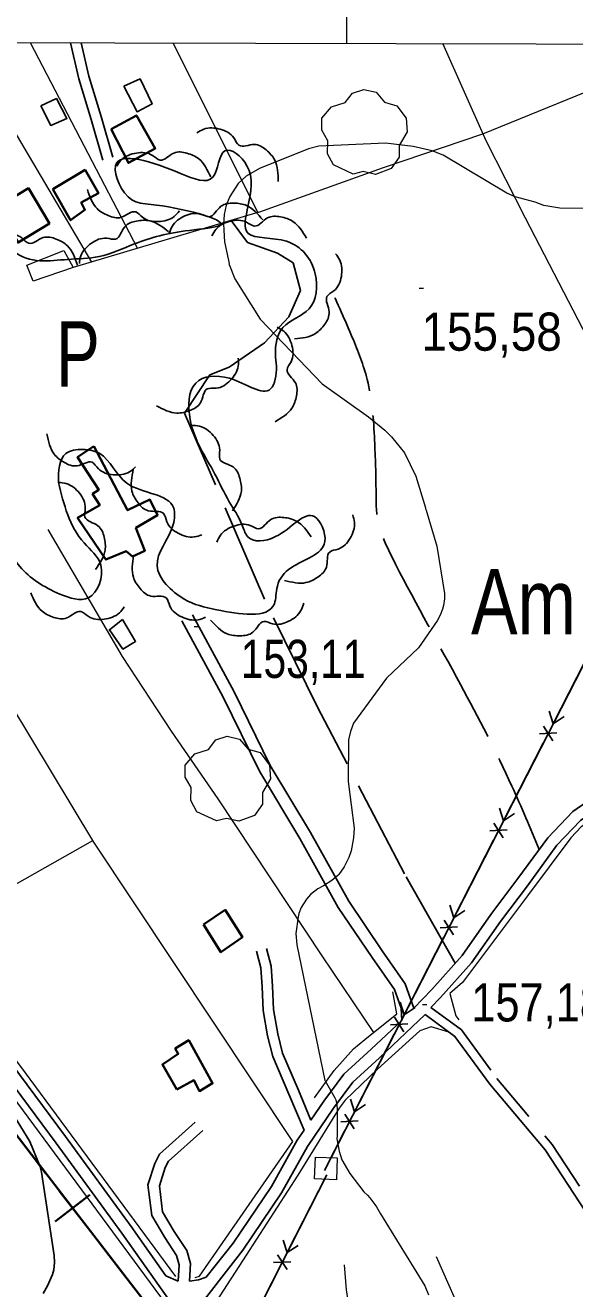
# Model space of a CAD drawing. Extents: x 480269 to 484877, y 4383588 to 4386804.
# Drawn here: x 481926.2 to 482052.3, y 4386167.5 to 4386457.3 of the extents above; entities that cross this region are included whole.
import ezdxf
from ezdxf.enums import TextEntityAlignment as Align

# ---------------------------------------------------------------- set-up
doc = ezdxf.new("R2010")
doc.units = 0
doc.header["$LTSCALE"] = 3.8
doc.linetypes.add('LONG_DASHED', pattern=[7.5, 6, -1.5])
doc.linetypes.add('MEDIUM_DASHED', pattern=[4.5, 3, -1.5])
for name, color, linetype, lineweight in [('1', 7, 'Continuous', 13), ('21', 7, 'Continuous', 25), ('25', 7, 'LONG_DASHED', 25), ('27', 7, 'Continuous', 25), ('29', 7, 'Continuous', 13), ('34', 7, 'Continuous', 35), ('38', 7, 'Continuous', 25), ('43', 7, 'Continuous', 25), ('47', 7, 'Continuous', 35), ('51', 7, 'Continuous', 13), ('7', 7, 'Continuous', 13), ('8', 7, 'Continuous', 25), ('9', 7, 'Continuous', 13)]:
    doc.layers.add(name, color=color, linetype=linetype, lineweight=lineweight)
doc.layers.add('31', color=7, linetype='Continuous')

msp = doc.modelspace()

# ---------------------------------------------------------------- linework, layer by layer
at = {"layer": '1'}
msp.add_line((482000, 4386453.1), (482000, 4386524.51), dxfattribs=at)
msp.add_lwpolyline([(480529.1, 4386456.6), (484105.5, 4386448.1), (484100.5, 4384135.8), (480523.1, 4384144.4)], close=True, dxfattribs=at)
at = {"layer": '21'}
for points in [[(481948.88, 4386443.31), (481951.89, 4386437.43), (481955.32, 4386439.2), (481952.57, 4386444.96)], [(481929.84, 4386438.77), (481932.1, 4386434.27), (481935.79, 4386435.9), (481933.4, 4386440.43)], [(481948.58, 4386320.95), (481951.55, 4386315.92), (481948.65, 4386314.18), (481945.56, 4386318.6)]]:
    msp.add_lwpolyline(points, close=True, dxfattribs=at)
at = {"layer": '25'}
msp.add_lwpolyline([(482024.84, 4386242.11), (482013.25, 4386262.59), (481993.26, 4386300.87), (481981.09, 4386325.62), (481962.8, 4386368.28), (481968.62, 4386377.07), (481973.05, 4386378.81), (481981.14, 4386384.42), (481986.72, 4386390.39), (481989.37, 4386396.4), (481987.72, 4386402.73), (481984.11, 4386405), (481977.23, 4386407.44), (481973.49, 4386412.5)], dxfattribs=at)
at = {"layer": '27'}
for points in [[(481965.63, 4386432.55), (481967.18, 4386433.41), (481970.98, 4386433.41), (481974.09, 4386431.43), (481975.25, 4386429.73), (481978.8, 4386429.91), (481981.5, 4386428.65), (481983.46, 4386426.35), (481984.27, 4386421.45)], [(481933.85, 4386352.38), (481939.74, 4386338.52), (481943.59, 4386333.4), (481940.75, 4386325.96), (481934.19, 4386326.79), (481925, 4386333.08), (481919.03, 4386350.08), (481914, 4386376.47), (481905.71, 4386382.56), (481891.92, 4386382.18), (481883.24, 4386378.3), (481881.08, 4386376.53), (481888.89, 4386360.03), (481903.22, 4386338.79), (481908.12, 4386325.76), (481906.15, 4386325), (481891.16, 4386335.05), (481883.69, 4386346.3), (481878.85, 4386354.87), (481871.54, 4386366.67), (481859.63, 4386367.99), (481852.4, 4386359.85), (481849.08, 4386354.52), (481843.2, 4386359.68), (481828.08, 4386359.42), (481826.24, 4386360.95), (481832.78, 4386366.42), (481846.83, 4386373.67), (481847.08, 4386376.88), (481846.69, 4386386.62), (481854.97, 4386387.4), (481860.65, 4386383.43), (481884.1, 4386388.3), (481894.03, 4386391.89), (481908.9, 4386395.37), (481914.31, 4386405.74), (481914.73, 4386414.05), (481923.39, 4386405.51), (481935.94, 4386403.55), (481943.21, 4386404.22), (481951.28, 4386407.11), (481963.89, 4386410.21), (481970.84, 4386411.41), (481955.1, 4386416.18), (481950.67, 4386417.23), (481946.94, 4386424.99), (481961.83, 4386423.29), (481969.28, 4386422.43), (481972.04, 4386428.47), (481977.09, 4386425.03), (481977.38, 4386409.52), (481986.17, 4386407.71), (481992.75, 4386400.23), (481991.34, 4386392.2), (481985.35, 4386387.92), (481983.62, 4386381.84), (481983.84, 4386379.05), (481982.52, 4386373.84), (481973.09, 4386376.28), (481965.35, 4386375.19), (481964.06, 4386366.87), (481969.75, 4386354.31), (481973.04, 4386347.96), (481975.95, 4386342.73), (481977.21, 4386340.01), (481983.66, 4386339.96), (481992.58, 4386344.55), (481994.96, 4386338.82), (481987.21, 4386332.83), (481984.07, 4386328.63), (481983.38, 4386324.54), (481970.2, 4386323.19), (481962.67, 4386325.66), (481956.48, 4386333.28), (481960.18, 4386342.74), (481960.29, 4386346.51), (481949.55, 4386352.22), (481943.31, 4386359.03), (481939.45, 4386359.96), (481935.55, 4386359), (481933.85, 4386352.38)], [(481947.24, 4386424.97), (481948.3, 4386426.38), (481951.76, 4386427.94), (481955.42, 4386427.41), (481957.17, 4386426.33), (481960.33, 4386427.95), (481963.32, 4386427.91), (481966.05, 4386426.61), (481968.79, 4386422.48)], [(481961.61, 4386414.67), (481960.38, 4386413.39), (481956.77, 4386412.24), (481953.2, 4386413.19), (481951.58, 4386414.46), (481948.25, 4386413.21), (481945.29, 4386413.6), (481942.73, 4386415.2), (481940.48, 4386419.62)], [(481959.26, 4386409.47), (481959.93, 4386411.12), (481962.87, 4386413.51), (481966.54, 4386413.94), (481968.5, 4386413.35), (481971.14, 4386415.73), (481974.04, 4386416.46), (481977.01, 4386415.91), (481980.73, 4386412.63)], [(481938.66, 4386402.59), (481938.99, 4386404.34), (481941.41, 4386407.26), (481944.92, 4386408.4), (481946.97, 4386408.21), (481949.09, 4386411.06), (481951.78, 4386412.35), (481954.81, 4386412.39), (481959.1, 4386409.9)], [(481969.05, 4386408.94), (481969.99, 4386410.45), (481973.3, 4386412.31), (481976.99, 4386412.1), (481978.82, 4386411.19), (481981.83, 4386413.08), (481984.81, 4386413.31), (481987.64, 4386412.26), (481990.75, 4386408.39)], [(481917.05, 4386406.89), (481918.25, 4386408.19), (481921.85, 4386409.4), (481925.43, 4386408.5), (481927.07, 4386407.26), (481930.38, 4386408.56), (481933.34, 4386408.22), (481935.93, 4386406.65), (481938.25, 4386402.27)], [(481997.42, 4386404.86), (481998.41, 4386403.39), (481998.75, 4386399.61), (481997.05, 4386396.33), (481995.46, 4386395.03), (481995.96, 4386391.51), (481994.94, 4386388.7), (481992.82, 4386386.55), (481988.02, 4386385.3)], [(481984.04, 4386388.01), (481985.55, 4386387.08), (481987.42, 4386383.78), (481987.22, 4386380.09), (481986.31, 4386378.25), (481988.22, 4386375.25), (481988.45, 4386372.27), (481987.41, 4386369.44), (481983.55, 4386366.32)], [(481975.11, 4386380.88), (481975.1, 4386379.1), (481973.26, 4386375.78), (481970.02, 4386374.02), (481967.97, 4386373.84), (481966.41, 4386370.64), (481963.99, 4386368.89), (481961.03, 4386368.3), (481956.35, 4386369.96)], [(481964.44, 4386365.46), (481966.2, 4386365.31), (481969.36, 4386363.2), (481970.85, 4386359.82), (481970.86, 4386357.77), (481973.91, 4386355.94), (481975.46, 4386353.39), (481975.81, 4386350.39), (481973.76, 4386345.87)], [(481951.55, 4386355.96), (481950.17, 4386354.84), (481946.44, 4386354.16), (481943.02, 4386355.55), (481941.58, 4386357.02), (481938.12, 4386356.21), (481935.23, 4386356.97), (481932.89, 4386358.88), (481931.22, 4386363.55)], [(481966.72, 4386340.39), (481965.02, 4386339.9), (481961.32, 4386340.74), (481958.72, 4386343.37), (481957.97, 4386345.28), (481954.47, 4386345.89), (481952.11, 4386347.72), (481950.71, 4386350.4), (481951.01, 4386355.36)], [(481933.85, 4386352.38), (481935.61, 4386352.15), (481938.67, 4386349.91), (481940.01, 4386346.47), (481939.94, 4386344.42), (481942.91, 4386342.46), (481944.35, 4386339.85), (481944.56, 4386336.83), (481942.33, 4386332.4)], [(481970.19, 4386338.7), (481971, 4386340.28), (481974.14, 4386342.4), (481977.84, 4386342.51), (481979.74, 4386341.75), (481982.58, 4386343.88), (481985.53, 4386344.35), (481988.44, 4386343.54), (481991.86, 4386339.94)], [(482001.36, 4386344.97), (482001.77, 4386343.24), (482000.76, 4386339.58), (481998.03, 4386337.11), (481996.08, 4386336.44), (481995.31, 4386332.97), (481993.38, 4386330.7), (481990.64, 4386329.42), (481985.7, 4386329.94)], [(481967.56, 4386321.47), (481965.88, 4386320.89), (481962.14, 4386321.54), (481959.41, 4386324.03), (481958.57, 4386325.9), (481955.04, 4386326.33), (481952.59, 4386328.04), (481951.05, 4386330.64), (481951.09, 4386335.61)], [(481948.95, 4386323.86), (481947.83, 4386322.47), (481944.32, 4386321.04), (481940.69, 4386321.69), (481938.98, 4386322.82), (481935.76, 4386321.31), (481932.78, 4386321.45), (481930.1, 4386322.84), (481927.49, 4386327.06)], [(481990.11, 4386324.69), (481989.49, 4386323.03), (481986.63, 4386320.54), (481982.98, 4386319.98), (481981, 4386320.51), (481978.44, 4386318.04), (481975.57, 4386317.22), (481972.58, 4386317.67), (481968.75, 4386320.83)]]:
    msp.add_spline(points, degree=3, dxfattribs=at)
at = {"layer": '29'}
for points in [[(482001.49, 4386423.13), (481996.95, 4386425.25), (481995.54, 4386427.79), (481995.64, 4386430.77), (481994.27, 4386433.18), (481994.31, 4386435.93), (481996.47, 4386438.53), (481999.66, 4386439.53), (482001.31, 4386441.72), (482003.88, 4386442.55), (482006.74, 4386441.9), (482008.69, 4386439.63), (482011.5, 4386438.81), (482013.63, 4386435.96), (482013.87, 4386432.83), (482011.99, 4386429.68), (482011.99, 4386427), (482010.17, 4386424.39), (482006.55, 4386423.05), (482003.78, 4386423.68)], [(481970.14, 4386274.75), (481965.6, 4386276.87), (481964.19, 4386279.41), (481964.29, 4386282.39), (481962.92, 4386284.8), (481962.96, 4386287.55), (481965.12, 4386290.15), (481968.31, 4386291.15), (481969.96, 4386293.34), (481972.53, 4386294.17), (481975.39, 4386293.52), (481977.34, 4386291.25), (481980.15, 4386290.43), (481982.28, 4386287.58), (481982.52, 4386284.45), (481980.64, 4386281.3), (481980.64, 4386278.62), (481978.82, 4386276.01), (481975.2, 4386274.67), (481972.43, 4386275.3)]]:
    msp.add_lwpolyline(points, close=True, dxfattribs=at)
at = {"layer": '34'}
for p, q in [((481924.89, 4386201.82), (481930.99, 4386193.9)), ((481933.13, 4386182.92), (481941.06, 4386189.02)), ((481934.04, 4386189.94), (481940.15, 4386182.01)), ((481943.2, 4386178.05), (481949.3, 4386170.13))]:
    msp.add_line(p, q, dxfattribs=at)
msp.add_lwpolyline([(481732.67, 4386453.74), (481770, 4386403), (482108, 4385964), (482722, 4385145)], dxfattribs=at)
at = {"layer": '38'}
msp.add_line((481958.52, 4386170.44), (481961.32, 4386169.19), dxfattribs=at)
for points in [[(481739.02, 4386453.72), (481746.6, 4386443.81), (481763.9, 4386421.1), (481780.66, 4386400.62), (481800.54, 4386375.74), (481816.44, 4386355.57), (481830.64, 4386336.1), (481844.6, 4386317.88), (481859.91, 4386297.65), (481877.97, 4386274.55), (481894.23, 4386252.79), (481912.43, 4386228.94), (481933.35, 4386200.86), (481948.43, 4386180.22), (481961.29, 4386161.94)], [(481939.06, 4386453.25), (481940.8, 4386445.59), (481943.63, 4386436.32), (481946.35, 4386426.97)], [(481782.92, 4386401.98), (481802.59, 4386377.37), (481818.53, 4386357.15), (481832.74, 4386337.67), (481846.68, 4386319.47), (481861.98, 4386299.25), (481880.05, 4386276.14), (481896.32, 4386254.37), (481914.52, 4386230.51), (481935.46, 4386202.41), (481950.56, 4386181.75), (481958.52, 4386170.44)], [(482198.57, 4386347.37), (482144.8, 4386321.02), (482124.83, 4386311.36), (482105.3, 4386301.8), (482096.79, 4386298.1), (482086.59, 4386294.29), (482075.34, 4386290.26), (482066.02, 4386286.27), (482058.26, 4386281.34), (482051.85, 4386276.96), (482046.13, 4386270.92), (482039.27, 4386261.52), (482033.05, 4386253.31), (482026.46, 4386243.91), (482019.48, 4386236.12), (482015.41, 4386231.85)], [(481964.6, 4386322.02), (481974.14, 4386304.4), (481982.43, 4386287.49), (481991.67, 4386272.12), (482000.44, 4386256.38), (482008.14, 4386245), (482013.41, 4386237.38), (482015.41, 4386231.85)], [(481962.15, 4386320.69), (481971.66, 4386303.13), (481979.98, 4386286.15), (481989.26, 4386270.73), (481998.06, 4386254.92), (482005.84, 4386243.43), (482010.91, 4386236.1), (482012.45, 4386231.85), (482012.6, 4386229.01)], [(482019.28, 4386231.97), (482021.47, 4386234.28), (482028.6, 4386242.22), (482035.25, 4386251.71), (482041.45, 4386259.9), (482048.22, 4386269.18), (482053.62, 4386274.89), (482059.75, 4386279.07), (482067.29, 4386283.86), (482076.34, 4386287.73), (482078.56, 4386288.52)], [(481981.6, 4386245.51), (481982.63, 4386241.45), (481982.96, 4386236.83), (481983.21, 4386231.5), (481984.16, 4386225.92), (481985.27, 4386221.47), (481988.9, 4386213.01), (481991.79, 4386206.15)], [(481964.71, 4386161.53), (481976.12, 4386176.27), (481985.04, 4386189.49), (481990.95, 4386200.09), (481996.94, 4386208.9), (482001.36, 4386214.86), (482007.47, 4386220.39), (482017.96, 4386230.35)], [(482012.6, 4386229.01), (482005.62, 4386222.38), (481999.34, 4386216.69), (481994.72, 4386210.48), (481991.79, 4386206.15)], [(482017.96, 4386230.35), (482024.8, 4386225.32), (482032.82, 4386214.38), (482045.48, 4386199.29), (482056.03, 4386183.18), (482065.57, 4386170.43), (482076.34, 4386154.94), (482088.98, 4386138), (482103.7, 4386117.74), (482125.67, 4386086.96), (482159.57, 4386041.91), (482175.62, 4386019.95), (482188.51, 4386002.59), (482205.17, 4385980.34)], [(481963.91, 4386169.23), (481964.15, 4386173.24), (481963.32, 4386176.2), (481960.43, 4386180.59), (481957.76, 4386185.08), (481957.01, 4386191.08), (481958.33, 4386195.23), (481959.1, 4386196.75), (481966.94, 4386203.76)], [(481990.19, 4386203.83), (481988.63, 4386201.51), (481982.72, 4386190.91), (481973.95, 4386177.92), (481967.74, 4386170.08)], [(481963.91, 4386169.23), (481965.98, 4386169.51), (481967.74, 4386170.08)]]:
    msp.add_lwpolyline(points, dxfattribs=at)
at = {"layer": '38', "linetype": 'MEDIUM_DASHED'}
for points in [[(481936.63, 4386453.25), (481938.5, 4386444.98), (481941.35, 4386435.64), (481944.07, 4386426.31)], [(481979.31, 4386244.92), (481980.28, 4386241.07), (481980.6, 4386236.69), (481980.85, 4386231.25), (481981.84, 4386225.43), (481983.02, 4386220.71), (481986.72, 4386212.08), (481990.19, 4386203.83)], [(482019.28, 4386231.97), (482026.29, 4386226.81), (482034.45, 4386215.66), (482047.15, 4386200.54), (482057.73, 4386184.38), (482067.26, 4386171.65), (482078.03, 4386156.16), (482090.65, 4386139.24), (482105.39, 4386118.96), (482127.35, 4386088.19), (482161.24, 4386043.15), (482177.29, 4386021.19), (482190.18, 4386003.84), (482206.83, 4385981.59)], [(481961.32, 4386169.19), (481961.55, 4386172.96), (481960.94, 4386175.12), (481958.24, 4386179.22), (481955.26, 4386184.22), (481954.38, 4386191.32), (481955.93, 4386196.21), (481957.02, 4386198.35), (481965.22, 4386205.68)]]:
    msp.add_lwpolyline(points, dxfattribs=at)
at = {"layer": '38', "linetype": 'LONG_DASHED'}
msp.add_spline([(482044.17, 4386268.23), (482037.88, 4386282.73), (482026.1, 4386306.05), (482011.21, 4386333.62), (482006.91, 4386345.18), (482006.71, 4386350.1), (482006.37, 4386362.09), (482004.68, 4386376.04), (482001.26, 4386385.67), (481996.06, 4386397.41)], degree=3, dxfattribs=at)
at = {"layer": '43'}
for p, q in [((482090.68, 4386381.61), (481994.87, 4386194.6)), ((482056.48, 4386314.86), (482047.36, 4386297.06)), ((482047.36, 4386297.06), (482046.44, 4386299.91)), ((482047.36, 4386297.06), (482049.88, 4386298.69)), ((482045.13, 4386296.52), (482047.3, 4386293.16)), ((482045.08, 4386292.61), (482035.96, 4386274.81)), ((482044.22, 4386294.74), (482048.21, 4386294.94)), ((482035.96, 4386274.81), (482035.04, 4386277.66)), ((482035.96, 4386274.81), (482038.48, 4386276.44)), ((482032.82, 4386272.49), (482036.81, 4386272.69)), ((482033.73, 4386274.27), (482035.9, 4386270.91)), ((482033.68, 4386270.36), (482024.56, 4386252.56)), ((482024.56, 4386252.56), (482023.64, 4386255.41)), ((482022.33, 4386252.02), (482024.5, 4386248.66)), ((482024.56, 4386252.56), (482027.09, 4386254.19)), ((482021.42, 4386250.24), (482025.41, 4386250.44)), ((482022.28, 4386248.11), (482013.17, 4386230.31)), ((482013.17, 4386230.31), (482012.25, 4386233.16)), ((482013.17, 4386230.31), (482015.69, 4386231.94)), ((482010.93, 4386229.77), (482013.1, 4386226.41)), ((482010.89, 4386225.86), (482001.77, 4386208.06)), ((482010.02, 4386227.99), (482014.01, 4386228.19)), ((482001.77, 4386208.06), (482000.85, 4386210.91)), ((482001.77, 4386208.06), (482004.29, 4386209.69)), ((481998.62, 4386205.74), (482002.61, 4386205.94)), ((481999.53, 4386207.52), (482001.7, 4386204.16)), ((481999.49, 4386203.61), (481994.87, 4386194.6)), ((481995.46, 4386193.59), (481699.21, 4385614.13)), ((481995.46, 4386193.59), (481986.36, 4386175.78)), ((481986.36, 4386175.78), (481985.43, 4386178.63)), ((481986.36, 4386175.78), (481988.87, 4386177.41)), ((481983.21, 4386173.46), (481987.2, 4386173.66)), ((481984.12, 4386175.24), (481986.29, 4386171.88)), ((481984.08, 4386171.33), (481974.98, 4386153.52))]:
    msp.add_line(p, q, dxfattribs=at)
at = {"layer": '43', "lineweight": 13}
msp.add_lwpolyline([(481992.61, 4386192.64), (481992.79, 4386197.64), (481997.79, 4386197.46), (481997.61, 4386192.46)], close=True, dxfattribs=at)
at = {"layer": '47'}
for points in [[(481945.96, 4386433.41), (481949.91, 4386425.67), (481956.07, 4386429.02), (481951.73, 4386436.59)], [(481932.57, 4386419.67), (481936.65, 4386412.55), (481939.93, 4386414.96), (481939.09, 4386416.57), (481943.01, 4386418.71), (481939.96, 4386424.09)], [(481919.69, 4386415.54), (481924.61, 4386407.41), (481931.79, 4386411.76), (481926.98, 4386419.89)], [(481941.94, 4386360.72), (481949.71, 4386346.03), (481954.84, 4386348.48), (481956.58, 4386344.9), (481951.63, 4386341.97), (481953.69, 4386336.72), (481950.87, 4386335.44), (481949.42, 4386336.63), (481944.74, 4386334.71), (481938.26, 4386344.26), (481943.34, 4386347.17), (481941.69, 4386349.77), (481943.11, 4386350.72), (481938.25, 4386358.17)], [(481967.12, 4386251.03), (481971.11, 4386244.64), (481976.04, 4386248.11), (481972.13, 4386254.35)], [(481961.04, 4386213.19), (481964.93, 4386215.29), (481966.21, 4386212.79), (481969.22, 4386214.6), (481963.74, 4386224.46), (481960.63, 4386222.54), (481961.33, 4386221.37), (481957.7, 4386218.87)]]:
    msp.add_lwpolyline(points, close=True, dxfattribs=at)
at = {"layer": '47', "lineweight": 13}
msp.add_lwpolyline([(481928.06, 4386398.58), (481926.62, 4386402.23), (481935.05, 4386405.62), (481937.21, 4386401.66)], close=True, dxfattribs=at)
at = {"layer": '51'}
for p, q in [((481911.64, 4386453.31), (481941.44, 4386402.92)), ((481927.39, 4386453.28), (481952, 4386406.08)), ((481960.13, 4386453.2), (481979.62, 4386414.33)), ((481979.84, 4386414.39), (481937.21, 4386401.66)), ((481902.47, 4386248.1), (481941.73, 4386270.28))]:
    msp.add_line(p, q, dxfattribs=at)
for points in [[(482056.85, 4386282.64), (482065, 4386286.82), (482072.5, 4386291.37), (482077.81, 4386292.89), (482091.79, 4386297.48), (482095.23, 4386302.21), (482081.96, 4386328.67), (482065.98, 4386362.19), (482057.43, 4386381.28), (482041.01, 4386413), (482031.94, 4386430.73), (482022.07, 4386453.05)], [(482031.22, 4386432.38), (482065.42, 4386446.28), (482081.77, 4386452.91)], [(481979.84, 4386414.39), (482008.45, 4386424.62), (482031.22, 4386432.38)], [(481817.91, 4386359.84), (481864.33, 4386298.51), (481900.1, 4386251.19), (481924.94, 4386218.71), (481960.73, 4386170.26)], [(481931.39, 4386341.62), (481948.49, 4386312.47), (481959.7, 4386295.31), (481970.43, 4386279.79)], [(481965.23, 4386170.04), (481966.18, 4386170.36), (481987.65, 4386201.24), (481941.95, 4386269.9), (481908.05, 4386326.13)], [(482277.59, 4386022.06), (482221, 4386098.74), (482171.74, 4386163.91), (482120.88, 4386231.42), (482079.09, 4386287.6), (482069.79, 4386283.22), (482063.21, 4386279.39), (482053.77, 4386273.42), (482051.37, 4386270.92), (482041.47, 4386257.57), (482026.53, 4386237.69), (482023.67, 4386235.19), (482025.03, 4386230.05), (482025.68, 4386229.13)], [(481970.43, 4386279.79), (481994.28, 4386243.84), (482006.16, 4386226.25)], [(481992.61, 4386211.21), (481997.13, 4386217.53), (482001.57, 4386222.47), (482004.16, 4386224.64), (482011.5, 4386230.55), (482010.6, 4386235.55)], [(481912.31, 4386226.42), (481959.65, 4386162.43), (481950.26, 4386151.47), (481940.96, 4386139.7), (481931.94, 4386128.9), (481927.03, 4386121.52), (481922.22, 4386112.8)], [(482023.44, 4386226.29), (482019.33, 4386227.52), (482016.76, 4386226.59), (482007.06, 4386217.8), (481999.62, 4386210.72), (481998.29, 4386208.84), (481988.8, 4386193.51), (481976.95, 4386175.19), (481970.07, 4386164.52), (481967.05, 4386161.75), (481982.65, 4386141.46), (482001.74, 4386116), (482022.8, 4386088.31), (482055.85, 4386042.59)], [(482020.49, 4386174.85), (482027.5, 4386159.12), (482033.11, 4386145.47), (482036.07, 4386137.23)], [(482002.75, 4386151.86), (482001.43, 4386157.19), (481999.92, 4386167.19), (481999.46, 4386172.98)]]:
    msp.add_lwpolyline(points, dxfattribs=at)
at = {"layer": '7'}
for p, q in [((482016.63, 4386396.98), (482017.63, 4386396.98)), ((481964.97, 4386319.33), (481965.97, 4386319.33)), ((482017.34, 4386232.64), (482018.34, 4386232.64))]:
    msp.add_line(p, q, dxfattribs=at)
at = {"layer": '8'}
msp.add_lwpolyline([(481930.32, 4386166.4), (481931.37, 4386168.16), (481932.48, 4386170.76), (481932.76, 4386171.8), (481932.92, 4386173.48), (481932.88, 4386175.11), (481929.95, 4386194.19), (481929.64, 4386195.41), (481927.26, 4386201.23), (481914.81, 4386221.42)], dxfattribs=at)
at = {"layer": '9'}
for points in [[(482055.61, 4386415.2), (482048.89, 4386415.28), (482045.19, 4386415.9), (482043.21, 4386416.7), (482038.6, 4386417.92), (482036.68, 4386418.71), (482022.1, 4386427.49), (482019.59, 4386428.46), (482015.21, 4386429.45), (482008.87, 4386430.18), (481993.6, 4386429.52), (481991.23, 4386428.92), (481979.97, 4386424.4), (481976.88, 4386422.67), (481975.12, 4386421), (481975.11, 4386420.99), (481975.1, 4386420.99), (481973.17, 4386418.01), (481972.34, 4386415.96), (481971.87, 4386413.82), (481971.75, 4386411.64), (481971.95, 4386407.56), (481972.99, 4386402.61), (481972.99, 4386402.6), (481972.98, 4386402.59), (481972.97, 4386402.56), (481973.03, 4386402.36), (481974.33, 4386399.13), (481980.1, 4386389.84), (481994.32, 4386374.99), (482004.95, 4386367.47), (482008.74, 4386364.4), (482010.28, 4386362.85), (482013.23, 4386359.15), (482015.83, 4386353.84), (482018.07, 4386346.59), (482018.09, 4386346.32), (482018.12, 4386346.2), (482018.19, 4386346.02), (482020.64, 4386337.77), (482022.41, 4386326.89), (482022.4, 4386325.69), (482022.18, 4386324.16), (482021.94, 4386323.3), (482021.42, 4386321.99), (482020.73, 4386320.65), (482016.42, 4386314.43), (482009.14, 4386307.48), (482001.57, 4386297.16), (482000.83, 4386295.3), (482000.4, 4386293.33), (482000.33, 4386283.78), (482001.66, 4386273.12), (482001.56, 4386270.9), (482001.02, 4386267.91), (482000.47, 4386266.35), (481999.41, 4386264.22), (481998.21, 4386262.51), (481997.96, 4386262.24), (481996.59, 4386261.08), (481994.67, 4386259.86), (481994.52, 4386259.82), (481993.37, 4386259.18), (481991.66, 4386257.86), (481990.77, 4386256.85), (481989.54, 4386254.94), (481989.02, 4386253.56), (481988.85, 4386252.79), (481988.32, 4386248.96), (481988.52, 4386246.37), (481994.97, 4386215.24), (481995.06, 4386215.17), (481997.26, 4386211.28), (481997.45, 4386210.76), (481997.71, 4386209.64), (481997.83, 4386208.49), (481997.76, 4386202.2), (481997.72, 4386202.11), (481997.7, 4386202.03), (481997.71, 4386201.82), (481998.23, 4386198.99), (481998.89, 4386197.04), (482000.73, 4386193.86), (482003.89, 4386189.7), (482004.75, 4386188.89), (482005.3, 4386188.31), (482006.69, 4386186.49)], [(482006.69, 4386186.49), (482006.81, 4386186.22), (482007.72, 4386184.62), (482017.93, 4386168.14), (482018.75, 4386166.05)]]:
    msp.add_lwpolyline(points, dxfattribs=at)

# ---------------------------------------------------------------- texts
at = {"layer": '31'}
for s, width, p in [('P', 0.75, (481938.33, 4386374.37)), ('Am', 0.8, (482040.53, 4386317.54))]:
    msp.add_text(s, height=15, dxfattribs=dict(at, width=width)).set_placement(p, align=Align.CENTER)
at = {"layer": '7'}
for s, width, p in [('155,58', 0.9, (482017.13, 4386382.61)), ('153,11', 0.8, (481975.68, 4386307.55)), ('157,18', 0.85, (482028.57, 4386228.76))]:
    msp.add_text(s, height=8.75, dxfattribs=dict(at, width=width)).set_placement(p)

doc.saveas('drawing.dxf')
